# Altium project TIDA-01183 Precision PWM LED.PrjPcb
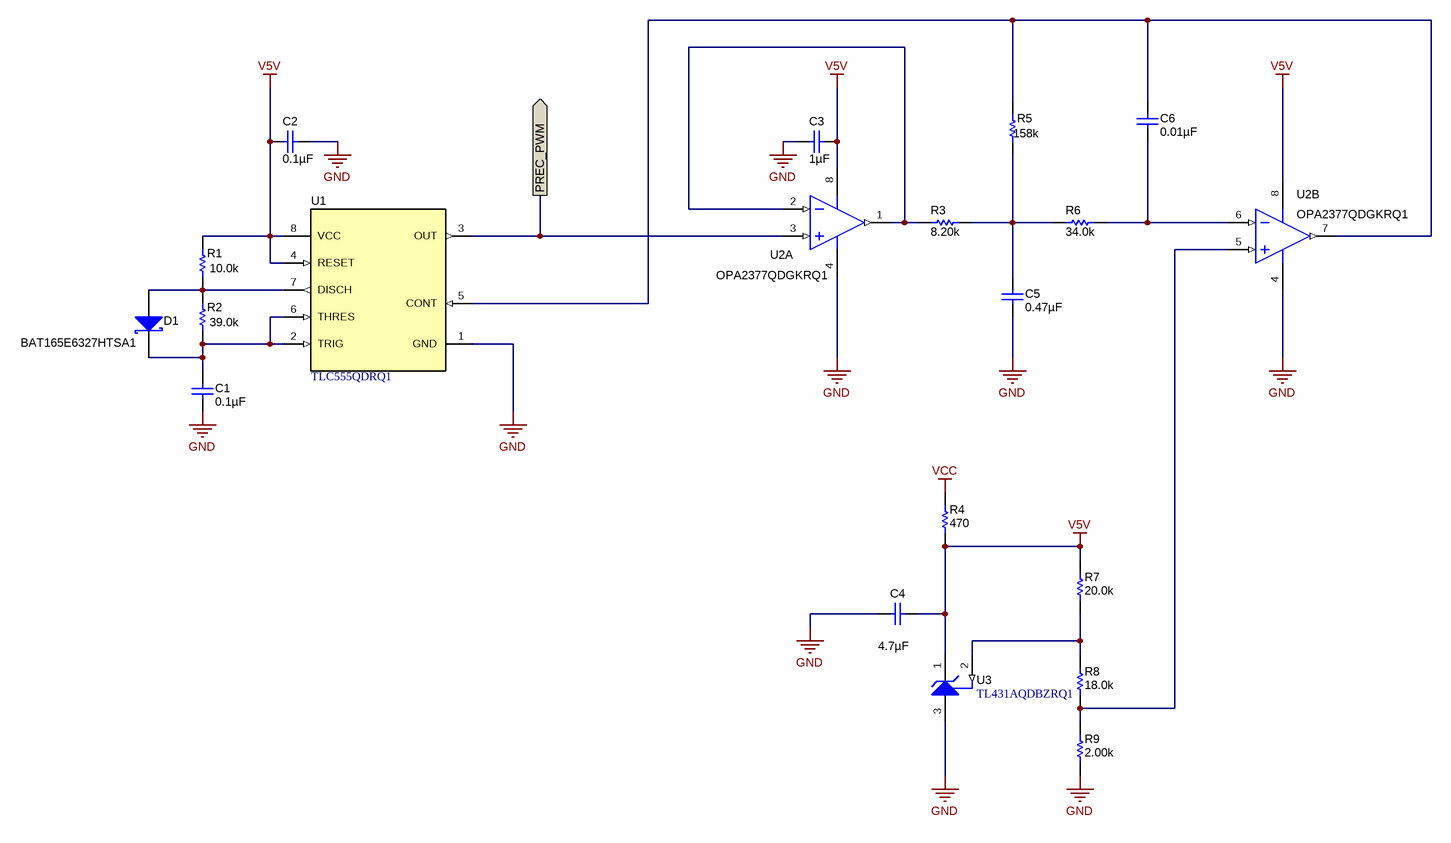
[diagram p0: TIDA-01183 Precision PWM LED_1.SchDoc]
CopyrightYear: 2016; EVM_Orderable: No; PCB_Layout: Robert Regensburger; PCB_Rev: B; PRJ_Customer: Public Release; PRJ_Engineer: Robert Regensburger; PRJ_Number: TIDA-01183; PRJ_Title: Precision PWM LED Dimming; SCH_Rev: B; TechSupport: http://www.ti.com/support; TID: N/A
3 sheets, 109 parts. Net scope: flat (ports and power ports of the same name join across sheets).
Board file: TIDA-01183 Precision PWM LED.PcbDoc
Sheets:
  TIDA-01183 Precision PWM LED_1.SchDoc
  TIDA-01183 Precision PWM LED_2.SchDoc
  TIDA-01183 Precision PWM LED_Hardware.SchDoc

## Sheet TIDA-01183 Precision PWM LED_1.SchDoc: Precision PWM Generator
size 431 x 279 mm; Date: Not shown in title block; ApprovedBy: Not shown in title block; CheckedBy: Not shown in title block; Author: Not shown in title block; CompanyName: Not shown in title block; DrawnBy: R. Regensburger; Engineer: Not shown in title block; Organization: Not shown in title block; Address1: Not shown in title block; Address2: Not shown in title block; Address3: Not shown in title block; Address4: Not shown in title block; DocumentNumber: 1; Revision: Use project parameter SCH_Rev; SheetNumber: 1; SheetTotal: 3; PageSetup: Record=PageOptions¦CenterHorizontal=True¦CenterVertical=True¦PrintScale=0.96¦XCorrection=1.00¦YCorrection=1.00¦PrintKind=0¦BorderSize=5000000¦LeftOffset=0¦BottomOffset=0¦Orientation=2¦PaperLength=1000¦PaperWidth=1000¦Scale=100¦PaperSource=15¦PrintQuality=-3¦MediaType=1¦DitherType=10¦PrintScaleMode=1¦PaperKind=11x17¦PaperIndex=3

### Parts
C1  ValueDisplayed: 0.1µF  [1206_190]  (hidden comment: C3216C0G2A104J160AC)
C2  ValueDisplayed: 0.1µF  [0603]  (hidden comment: 0603YC104JAT2A)
C3  ValueDisplayed: 1µF  [0603]  (hidden comment: GRM188R71C105KA12D)
C4  ValueDisplayed: 4.7µF  [0603]  (hidden comment: GRM188R61C475KAAJ)
C5  ValueDisplayed: 0.47µF  [0603]  (hidden comment: GRM188R71E474KA12D)
C6  ValueDisplayed: 0.01µF  [0603]  (hidden comment: GRM188R71C103KA01D)
D1  BAT165E6327HTSA1  [SOD-323]
R1  ValueDisplayed: 10.0k  [0603]  (hidden comment: CRCW060310K0FKEA)
R2  ValueDisplayed: 39.0k  [0603]  (hidden comment: RC0603FR-0739KL)
R3  ValueDisplayed: 8.20k  [0603]  (hidden comment: RC0603FR-078K2L)
R4  ValueDisplayed: 470  [0603]  (hidden comment: CRCW0603470RJNEA)
R5  ValueDisplayed: 158k  [0603]  (hidden comment: CRCW0603158KFKEA)
R6  ValueDisplayed: 34.0k  [0603]  (hidden comment: CRCW060334K0FKEA)
R7  ValueDisplayed: 20.0k  [0603]  (hidden comment: RG1608P-203-B-T5)
R8  ValueDisplayed: 18.0k  [0603]  (hidden comment: RG1608P-183-B-T5)
R9  ValueDisplayed: 2.00k  [0603]  (hidden comment: RG1608P-202-B-T5)
U1  TLC555QDRQ1  [D0008A_M]
U2  OPA2377QDGKRQ1  [DGK0008A_N]  (parts A,B of 2)
U3  TL431AQDBZRQ1  [DBZ0003A_N]

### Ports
PREC_PWM (out)

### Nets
GND: C1.2 C2.2 C3.1 C4.2 C5.2 R9.1 U1.1(GND) U2.4(V-) U3.3(ANODE)
V5V: C2.1 C3.2 C4.1 R1.2 R4.1 R7.2 U1.4(RESET) U1.8(VCC) U2.8(V+) U3.1(CATHODE)
VCC: R4.2
PREC_PWM: U1.3(OUT) U2.3(IN_A+) ; port PREC_PWM
NetC1_1: C1.1 D1.1(K) R2.1 U1.2(TRIG) U1.6(THRES)
NetC5_1: C5.1 R3.2 R5.1 R6.1
NetC6_1: C6.1 R5.2 U1.5(CONT) U2.7(OUT_B)
NetC6_2: C6.2 R6.2 U2.6(IN_B-)
NetD1_2: D1.2(A) R1.1 R2.2 U1.7(DISCH)
NetR3_1: R3.1 U2.1(OUT_A) U2.2(IN_A-)
NetR7_1: R7.1 R8.2 U3.2(REF)
NetR8_1: R8.1 R9.2 U2.5(IN_B+)

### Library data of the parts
C1 = C3216C0G2A104J160AC: CAP, CERM, 0.1 µF, 100 V, +/- 5%, C0G/NP0, 1206_190; Manufacturer: TDK; Polarized: N; CompType: Capacitor; Value: 0.1uF; U/M: EA; Cap_F: 0.0000001; Tolerance_%: 5; Value1: Unknown; VDC_V: 100; Value2: 100V; TaMin_C: -55; TaMax_C: 125; Cap_Case: 1206; SizeArea_mm2: 5.12; SizeAreaWB_mm2: 10.92; SizeX_mm: 3.2; SizeY_mm: 1.6; SizeZ_mm: 1.9; AEC Category: Q200
C2 = 0603YC104JAT2A: CAP, CERM, 0.1 µF, 16 V, +/- 5%, X7R, 0603; Manufacturer: AVX; Polarized: N; CompType: Capacitor; Value: 0.1uF; U/M: EA; Cap_F: 0.0000001; Tolerance_%: 5; ESR_ohm: 0.039; Value1: 0.039 ohm; VDC_V: 16; Value2: 16V; TaMin_C: -55; TaMax_C: 125; AEC Category: Q200
C3 = GRM188R71C105KA12D: CAP, CERM, 1 µF, 16 V, +/- 10%, X7R, 0603; Manufacturer: MuRata; Polarized: N; CompType: Capacitor; Value: 1uF; U/M: EA; Cap_F: 0.000001; Tolerance_%: 10; ESR_ohm: 0.011; Value1: 0.011 ohm; VDC_V: 16; Value2: 16V; TaMin_C: -55; TaMax_C: 125; AEC Category: Q200
C4 = GRM188R61C475KAAJ: CAP, CERM, 4.7 µF, 16 V, +/- 10%, X5R, 0603; Manufacturer: MuRata; Polarized: N; CompType: Capacitor; Value: 4.7uF; U/M: EA; Cap_F: 0.0000047; Tolerance_%: 10; Value1: Unknown; VDC_V: 16; Value2: 16V; TaMin_C: -55; TaMax_C: 85; AEC Category: Q200
C5 = GRM188R71E474KA12D: CAP, CERM, 0.47 µF, 25 V, +/- 10%, X7R, 0603; Manufacturer: MuRata; Polarized: N; CompType: Capacitor; Value: 0.47uF; U/M: EA; Cap_F: 0.00000047; Tolerance_%: 10; Value1: Unknown; VDC_V: 25; Value2: 25V; TaMin_C: -55; TaMax_C: 125; AEC Category: Q200
C6 = GRM188R71C103KA01D: CAP, CERM, 0.01 µF, 16 V, +/- 10%, X7R, 0603; Manufacturer: MuRata; Polarized: N; CompType: Capacitor; Value: 0.01uF; U/M: EA; Cap_F: 0.00000001; Tolerance_%: 10; Value1: Unknown; VDC_V: 16; Value2: 16V; TaMin_C: -55; TaMax_C: 125; AEC Category: Q200
D1 = BAT165E6327HTSA1: Diode, Schottky, 40 V, 0.75 A, AEC-Q101, SOD-323; Manufacturer: Infineon Technologies; U/M: EA; Vf_V: 0.74; Value: 40V; Value1: 0.75A; Value2: 0.74V; Io_A: 0.75; Vr_V: 40; TJmax_C: 150; SizeAreaWB_mm2: 8.695; SizeArea_mm2: 3.645; SizeX_mm: 2.7; SizeY_mm: 1.35; SizeZ_mm: 1; AEC Category: Q101; AEC Qualified: Y
R1 = CRCW060310K0FKEA: RES, 10.0 k, 1%, 0.1 W, 0603; Manufacturer: Vishay-Dale; CompType: Resistor; Value: 10.0k; Res_ohm: 10000; Value_Code: 10k0; Tolerance_%: 1; Power_W: 0.1; Value2: 0.1W; VDC_V: 75; TempCo: 100 ppm/C; SizeArea_mm2: 1.28; SizeX_mm: 1.6; SizeY_mm: 0.8; EIA_Code: E96; U/M: EA; AEC Category: Q200
R2 = RC0603FR-0739KL: RES, 39.0 k, 1%, 0.1 W, 0603; Manufacturer: Yageo America; CompType: Resistor; Value: 39.0k; Res_ohm: 39000; Value_Code: 39k0; Tolerance_%: 1; Power_W: 0.1; Value2: 0.1W; VDC_V: 150; TempCo: 200 ppm/C; SizeArea_mm2: 1.28; SizeX_mm: 1.6; SizeY_mm: 0.8; U/M: EA; AEC Category: Q200
R3 = RC0603FR-078K2L: RES, 8.20 k, 1%, 0.1 W, 0603; Manufacturer: Yageo America; CompType: Resistor; Value: 8.20k; Res_ohm: 8200; Value_Code: 8k20; Tolerance_%: 1; Power_W: 0.1; Value2: 0.1W; VDC_V: 150; TempCo: 200 ppm/C; U/M: EA; AEC Category: Q200
R4 = CRCW0603470RJNEA: RES, 470, 5%, 0.1 W, 0603; Manufacturer: Vishay-Dale; CompType: Resistor; Value: 470; Value_Code: 470R; Tolerance_%: 5; Power_W: 0.1; Value2: 0.1W; VDC_V: 75; TempCo: 200 ppm/C; EIA_Code: E24; U/M: EA; AEC Category: Q200
R5 = CRCW0603158KFKEA: RES, 158 k, 1%, 0.1 W, 0603; Manufacturer: Vishay-Dale; CompType: Resistor; Value: 158k; Res_ohm: 158000; Tolerance_%: 1; Power_W: 0.1; Value2: 0.1W; VDC_V: 75; TempCo: 100 ppm/C; EIA_Code: E96; U/M: EA; AEC Category: Q200
R6 = CRCW060334K0FKEA: RES, 34.0 k, 1%, 0.1 W, 0603; Manufacturer: Vishay-Dale; CompType: Resistor; Value: 34.0k; Res_ohm: 34000; Value_Code: 34k0; Tolerance_%: 1; Power_W: 0.1; Value2: 0.1W; VDC_V: 75; TempCo: 100 ppm/C; EIA_Code: E96; U/M: EA; AEC Category: Q200
R7 = RG1608P-203-B-T5: RES, 20.0 k, 0.1%, 0.1 W, 0603; Manufacturer: Susumu Co Ltd; CompType: Resistor; Value: 20.0k; Res_ohm: 20000; Value_Code: 20k0; Tolerance_%: 0.1; Value2: 0.1W; VDC_V: 75; TempCo: 25 ppm/C; EIA_Code: E192; U/M: EA; AEC Category: Q200
R8 = RG1608P-183-B-T5: RES, 18.0 k, 0.1%, 0.1 W, 0603; Manufacturer: Susumu Co Ltd; CompType: Resistor; Value: 18.0k; Res_ohm: 18000; Value_Code: 18k0; Tolerance_%: 0.1; Value2: 0.1W; VDC_V: 75; TempCo: 25 ppm/C; EIA_Code: E192; U/M: EA; AEC Category: Q200
R9 = RG1608P-202-B-T5: RES, 2.00 k, 0.1%, 0.1 W, 0603; Manufacturer: Susumu Co Ltd; CompType: Resistor; Value: 2.00k; Res_ohm: 2000; Value_Code: 2k00; Tolerance_%: 0.1; Value2: 0.1W; VDC_V: 75; TempCo: 25 ppm/C; EIA_Code: E192; U/M: EA; AEC Category: Q200
U1 = TLC555QDRQ1: LinCMOS Timer, D0008A; Manufacturer: Texas Instruments; SymbolCreator: a0799628; CompType: IC; U/M: EA
U2 = OPA2377AIDGKR: Low-Cost, Low Noise, 5 MHz CMOS Operational Amplifier, 2.2 to 5.5 V, -40 to 125 degC, 8-pin SOP (DGK0008A), Green (RoHS & no Sb/Br); Manufacturer: Texas Instruments; Alternate PartNumber: Equivalent; CMRR(Min)(dB): 70; IIB(Max)(pA): 10; Iq per channel(Max)(mA): 1.05; Number of Channels: 2; Offset Drift(Typ)(uV/C): 0.32; Sub Family: Low Input Bias Current Amp (<=10pA), Low Noise Amp (<=10nV/rtHz), Low Supply Voltage Amplifier (<=2.7V), Precision Amplifier; Total Supply Voltage(Max)(+5V is 5, +/-5V is 10): 5.5; Total Supply Voltage(Min)(+5V is 5, +/-5V is 10): 2.2; Vio (25C)(Max)(mV): 1; Vn at 1kHz(Typ)(nV/rtHz): 7.5
U3 = TL431AQDBZRQ1: Automotive Catalog Adjustable Precision Shunt Regulator, 34 ppm / degC, 100 mA, -40 to 125 degC, 3-pin SOT-23 (DBZ), Green (RoHS & no Sb/Br); Manufacturer: Texas Instruments; Alternate PartNumber: Equivalent; Iout/Iz(Max)(mA): 100; Min Iz for Regulation(uA): 600; SubFamily: Shunt Voltage Reference; Temp Coeff(Typ)(ppm/ degree C): 34; VO Adj(Max)(V): 36; VO Adj(Min)(V): 2.495; Initial Accuracy @ 25/deg C(%): 1

## Sheet TIDA-01183 Precision PWM LED_2.SchDoc: Buck-Boost LED Driver
size 431 x 279 mm; Date: Not shown in title block; ApprovedBy: Not shown in title block; CheckedBy: Not shown in title block; Author: Not shown in title block; CompanyName: Not shown in title block; DrawnBy: R. Regensburger; Engineer: Not shown in title block; Organization: Not shown in title block; Address1: Not shown in title block; Address2: Not shown in title block; Address3: Not shown in title block; Address4: Not shown in title block; DocumentNumber: 2; Revision: Use project parameter SCH_Rev; SheetNumber: 2; SheetTotal: 3; PageSetup: Record=PageOptions¦CenterHorizontal=True¦CenterVertical=True¦PrintScale=0.61¦XCorrection=1.00¦YCorrection=1.00¦PrintKind=0¦BorderSize=5000000¦LeftOffset=0¦BottomOffset=0¦Orientation=2¦PaperLength=1000¦PaperWidth=1000¦Scale=100¦PaperSource=15¦PrintQuality=600¦MediaType=1¦DitherType=10¦PrintScaleMode=1¦PaperKind=Letter
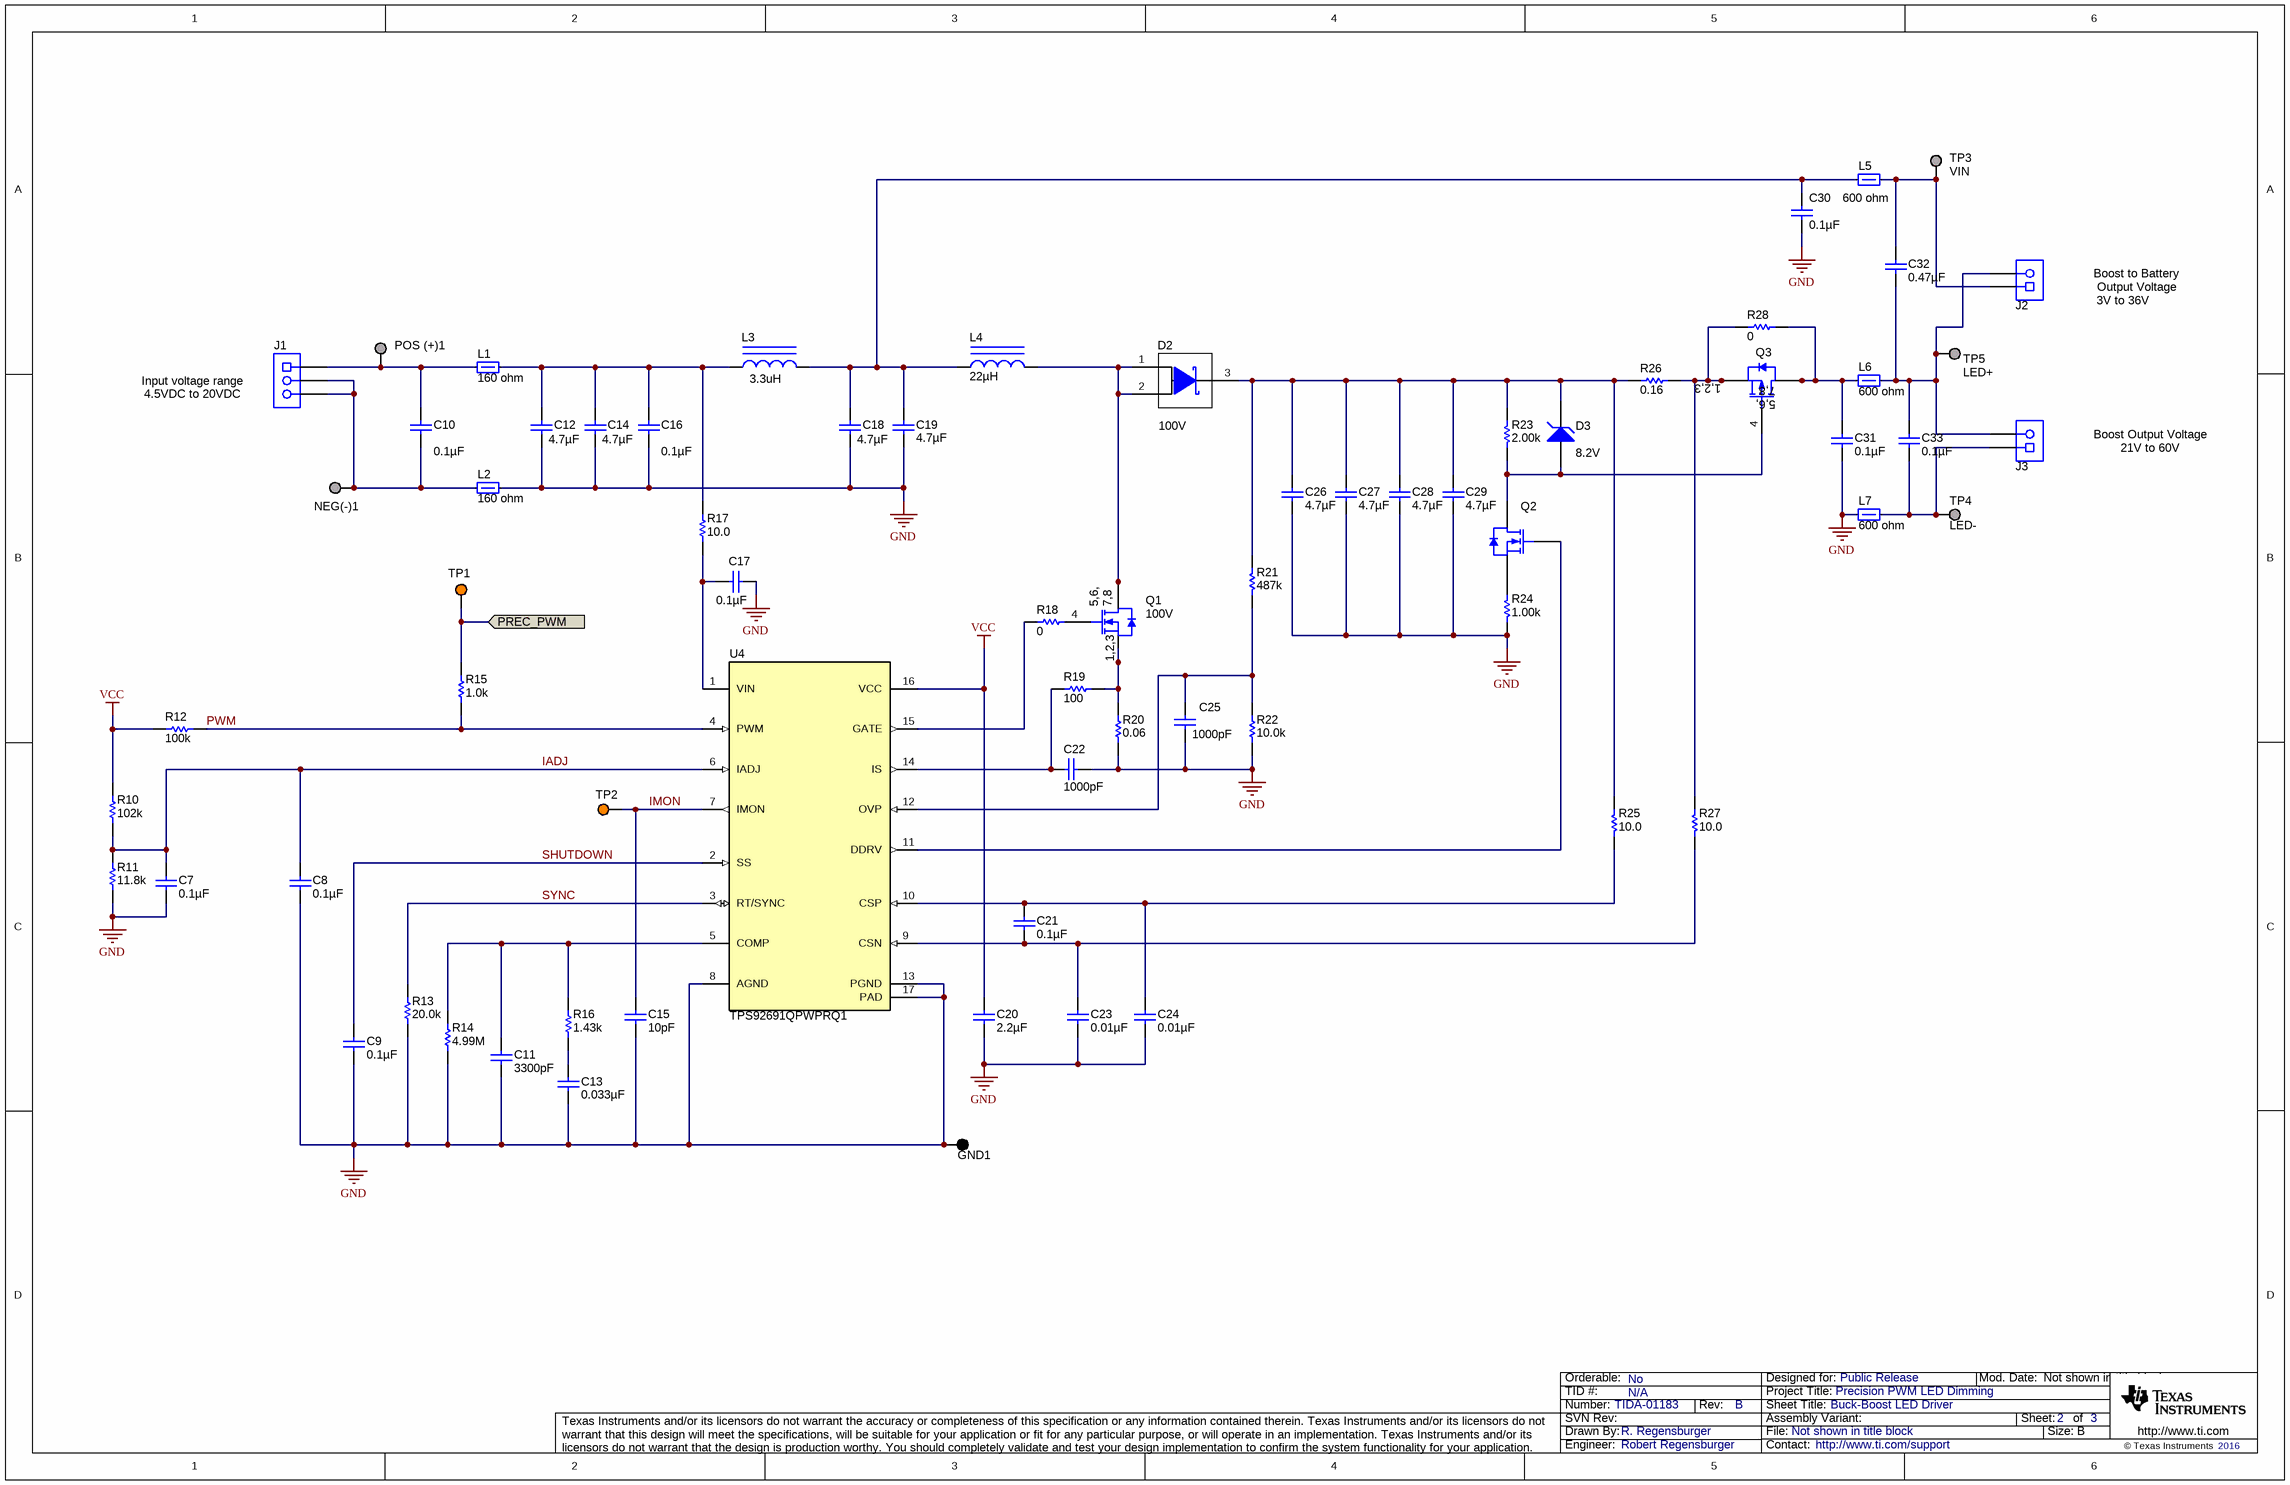
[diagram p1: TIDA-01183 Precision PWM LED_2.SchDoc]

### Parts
C7  ValueDisplayed: 0.1µF  [0603]  (hidden comment: 06033C104JAT2A)
C8  ValueDisplayed: 0.1µF  [0603]  (hidden comment: 06033C104JAT2A)
C9  ValueDisplayed: 0.1µF  [0603]  (hidden comment: 06033C104JAT2A)
C10  ValueDisplayed: 0.1µF  [0805_HV]  (hidden comment: C2012X7R2A104K125AA)
C11  ValueDisplayed: 3300pF  [0603]  (hidden comment: GRM188R71E332KA01D)
C12  ValueDisplayed: 4.7µF  [1210]  (hidden comment: C3225X7S2A475K200AE)
C13  ValueDisplayed: 0.033µF  [0805_HV]  (hidden comment: GRM216R71E333KA01D)
C14  ValueDisplayed: 4.7µF  [1210]  (hidden comment: C3225X7S2A475K200AE)
C15  ValueDisplayed: 10pF  [0603]  (hidden comment: 06035A100JAT2A)
C16  ValueDisplayed: 0.1µF  [0805_HV]  (hidden comment: C2012X7R2A104K125AA)
C17  ValueDisplayed: 0.1µF  [0805_HV]  (hidden comment: C2012X7R2A104K125AA)
C18  ValueDisplayed: 4.7µF  [1210]  (hidden comment: C3225X7S2A475K200AE)
C19  ValueDisplayed: 4.7µF  [1210]  (hidden comment: C3225X7S2A475K200AE)
C20  ValueDisplayed: 2.2µF  [0805_HV]  (hidden comment: C0805C225K4RACTU)
C21  ValueDisplayed: 0.1µF  [0603]  (hidden comment: GRM188R71H104KA93D)
C22  ValueDisplayed: 1000pF  [0603]  (hidden comment: GRM1885C2A102JA01D)
C23  ValueDisplayed: 0.01µF  [0603]  (hidden comment: CGA3E2X7R2A103K080AA)
C24  ValueDisplayed: 0.01µF  [0603]  (hidden comment: CGA3E2X7R2A103K080AA)
C25  ValueDisplayed: 1000pF  [0603_HV]  (hidden comment: C1608C0G2A102J080AA)
C26  ValueDisplayed: 4.7µF  [1210]  (hidden comment: C3225X7S2A475K200AE)
C27  ValueDisplayed: 4.7µF  [1210]  (hidden comment: C3225X7S2A475K200AE)
C28  ValueDisplayed: 4.7µF  [1210]  (hidden comment: C3225X7S2A475K200AE)
C29  ValueDisplayed: 4.7µF  [1210]  (hidden comment: C3225X7S2A475K200AE)
C30  ValueDisplayed: 0.1µF  [1206_180]  (hidden comment: C3216X7R2A104K160AA)
C31  ValueDisplayed: 0.1µF  [1206_180]  (hidden comment: C3216X7R2A104K160AA)
C32  ValueDisplayed: 0.47µF  [1206_180]  (hidden comment: C3216X7R2A474K160AA)
C33  ValueDisplayed: 0.1µF  [1206_180]  (hidden comment: C3216X7R2A104K160AA)
D2  value 100V  [PowerDI5]  (hidden comment: PDS3100Q-13)
D3  value 8.2V  [sod-323]  (hidden comment: MMSZ5237BS-7-F)
GND1  5001  [Keystone5001]  (value not drawn)
J1  1727023  [Phoenix_1727023]  (value not drawn)
J2  1727010  [PhoenixConact_1727010]  (value not drawn)
J3  1727010  [PhoenixConact_1727010]  (value not drawn)
L1  value 160 ohm  [1206]  (hidden comment: HI1206T161R-10)
L2  value 160 ohm  [1206]  (hidden comment: HI1206T161R-10)
L3  value 3.3uH  [CLF7045]  (hidden comment: CLF7045T-3R3N)
L4  ValueDisplayed: 22µH  [IHLP-4040DZ]  (hidden comment: IHLP4040DZER220M8A)
L5  value 600 ohm  [1206]  (hidden comment: MI1206K601R-10)
L6  value 600 ohm  [1206]  (hidden comment: MI1206K601R-10)
L7  value 600 ohm  [1206]  (hidden comment: MI1206K601R-10)
NEG(-)1  GND  [Keystone1502-2]  (value not drawn)
POS_(+)1  Suggest using a net name here  [Keystone1502-2]  (value not drawn)
Q1  value 100V  [PowerFLAT5x6_R]  (hidden comment: STL8N10LF3)
Q2  DMN10H220L-7  [SOT-23]  (value not drawn)
Q3  SI7415DN-T1-GE3  [PowerPAK_1212-8]  (value not drawn)
R10  ValueDisplayed: 102k  [0603]  (hidden comment: CRCW0603102KFKEA)
R11  ValueDisplayed: 11.8k  [0603]  (hidden comment: CRCW060311K8FKEA)
R12  ValueDisplayed: 100k  [0603]  (hidden comment: CRCW0603100KFKEA)
R13  ValueDisplayed: 20.0k  [0603]  (hidden comment: CRCW060320K0FKEA)
R14  ValueDisplayed: 4.99M  [0603]  (hidden comment: CRCW06034M99FKEA)
R15  ValueDisplayed: 1.0k  [0603]  (hidden comment: CRCW06031K00JNEA)
R16  ValueDisplayed: 1.43k  [0603]  (hidden comment: CRCW06031K43FKEA)
R17  ValueDisplayed: 10.0  [1206]  (hidden comment: CRCW120610R0FKEA)
R18  ValueDisplayed: 0  [0603_HV]  (hidden comment: CRCW06030000Z0EA)
R19  ValueDisplayed: 100  [0603_HV]  (hidden comment: CRCW0603100RFKEA)
R20  ValueDisplayed: 0.06  [2010]  (hidden comment: CSRN2010FK60L0)
R21  ValueDisplayed: 487k  [0603_HV]  (hidden comment: CRCW0603487KFKEA)
R22  ValueDisplayed: 10.0k  [0603_HV]  (hidden comment: CRCW060310K0FKEA)
R23  ValueDisplayed: 2.00k  [0603_HV]  (hidden comment: CRCW06032K00FKEA)
R24  ValueDisplayed: 1.00k  [1206]  (hidden comment: CRCW12061K00FKEA)
R25  ValueDisplayed: 10.0  [0603_HV]  (hidden comment: CRCW060310R0FKEA)
R26  ValueDisplayed: 0.16  [1210]  (hidden comment: MCR25JZHFLR160)
R27  ValueDisplayed: 10.0  [0603_HV]  (hidden comment: CRCW060310R0FKEA)
R28  ValueDisplayed: 0  [1206]  (hidden comment: CRCW12060000Z0EA)
TP1  5003  [Keystone5003]  (value not drawn)
TP2  5003  [Keystone5003]  (value not drawn)
TP3  VIN  [Keystone1502-2]
TP4  LED-  [Keystone1502-2]
TP5  LED+  [Keystone1502-2]
U4  TPS92691QPWPRQ1  [PWP0016J_N]

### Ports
PREC_PWM (in)

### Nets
GND: C7.2 C8.2 C9.2 C11.2 C12.2 C13.1 C14.2 C15.2 C16.2 C17.1 C18.2 C19.2 C20.2 C22.2 C23.2 C24.2 C25.2 C26.1 C27.1 C28.1 C29.1 C30.2 C31.2 GND1.1 L2.2 L7.1 R11.1 R13.1 R14.1 R20.1 R22.1 R24.1 U4.8(AGND) U4.13(PGND) U4.17(PAD)
VCC: C20.1 R10.2 R12.1 U4.16(VCC)
IADJ: C7.1 C8.1 R10.1 R11.2 U4.6(IADJ)
IMON: C15.1 TP2.1 U4.7(IMON)
PREC_PWM: R15.1 TP1.1 ; port PREC_PWM
PWM: R12.2 R15.2 U4.4(PWM)
SHUTDOWN: C9.1 U4.2(SS)
SYNC: R13.2 U4.3(RT/SYNC)
NetC10_1: C10.1 J1.1 L1.1 POS_(+)1.1
NetC10_2: C10.2 J1.2 J1.3 L2.1 NEG(-)1.1
NetC11_1: C11.1 R14.2 R16.2 U4.5(COMP)
NetC12_1: C12.1 C14.1 C16.1 L1.2 L3.1 R17.2
NetC13_2: C13.2 R16.1
NetC17_2: C17.2 R17.1 U4.1(VIN)
NetC18_1: C18.1 C19.1 C30.1 L3.2 L4.1 L5.1
NetC21_1: C21.1 C24.1 R25.1 U4.10(CSP)
NetC21_2: C21.2 C23.1 R27.1 U4.9(CSN)
NetC22_1: C22.1 R19.1 U4.14(IS)
NetC25_1: C25.1 R21.1 R22.2 U4.12(OVP)
NetC26_2: C26.2 C27.2 C28.2 C29.2 D2.3(K) D3.1(K) R21.2 R23.2 R25.2 R26.1
NetC31_1: C31.1 L6.1 Q3.5(D) Q3.6(D) Q3.7(D) Q3.8(D) Q3.9(D) R28.1
NetC32_1: C32.1 J2.1 L5.2 TP3.1
NetC32_2: C32.2 C33.1 J2.2 J3.2 L6.2 TP5.1
NetC33_2: C33.2 J3.1 L7.2 TP4.1
NetD2_1: D2.1(A) D2.2(A) L4.2 Q1.5(D) Q1.6(D) Q1.7(D) Q1.8(D) Q1.9(D)
NetD3_2: D3.2(A) Q2.3(D) Q3.4(G) R23.1
NetQ1_1: Q1.1(S) Q1.2(S) Q1.3(S) R19.2 R20.2
NetQ1_4: Q1.4(G) R18.2
NetQ2_1: Q2.1(G) U4.11(DDRV)
NetQ2_2: Q2.2(S) R24.2
NetQ3_1: Q3.1(S) Q3.2(S) Q3.3(S) R26.2 R27.2 R28.2
NetR18_1: R18.1 U4.15(GATE)

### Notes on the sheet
- 3V to 36V
- Boost to Battery
- Output Voltage
- 4.5VDC to 20VDC
- (near J1) Input voltage range
- Boost Output Voltage
- 21V to 60V

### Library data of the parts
C7-C9 = 06033C104JAT2A: CAP, CERM, 0.1 µF, 25 V, +/- 5%, X7R, 0603; Manufacturer: AVX; Polarized: N; CompType: Capacitor; Value: 0.1uF; U/M: EA; Cap_F: 0.0000001; Tolerance_%: 5; ESR_ohm: 0.05; Value1: 0.05 ohm; VDC_V: 25; Value2: 25V; TaMin_C: -55; TaMax_C: 125; SizeArea_mm2: 1.28; SizeAreaWB_mm2: 4.68; SizeX_mm: 1.6; SizeY_mm: 0.8; SizeZ_mm: 1; AEC Category: Q200
C10 C16 C17 = C2012X7R2A104K125AA: CAP, CERM, 0.1 µF, 100 V, +/- 10%, X7R, 0805; Manufacturer: TDK; Polarized: N; CompType: Capacitor; Value: 0.1uF; U/M: EA; Cap_F: 0.0000001; Tolerance_%: 10; ESR_ohm: 0.0158; Value1: 0.0158 ohm; VDC_V: 100; Value2: 100V; TaMin_C: -55; TaMax_C: 125; Cap_Case: 0805; AEC Category: Q200
C11 = GRM188R71E332KA01D: CAP, CERM, 3300 pF, 25 V, +/- 10%, X7R, 0603; Manufacturer: MuRata; Polarized: N; CompType: Capacitor; Value: 3300pF; U/M: EA; Cap_F: 0.0000000033; Tolerance_%: 10; Value1: Unknown; VDC_V: 25; Value2: 25V; TaMin_C: -55; TaMax_C: 125; AEC Category: Q200
C12 C14 C18 C19 C26-C29 = C3225X7S2A475K200AE: CAP, CERM, 4.7 µF, 100 V, +/- 10%, X7S, 1210; Manufacturer: TDK; Polarized: N; CompType: Capacitor; Value: 4.7uF; U/M: EA; Cap_F: 0.0000047; Tolerance_%: 10; Value1: Unknown; VDC_V: 100; Value2: 100V; TaMin_C: -55; TaMax_C: 125
C13 = GRM216R71E333KA01D: CAP, CERM, 0.033 µF, 25 V, +/- 10%, X7R, 0805; Manufacturer: MuRata; Polarized: N; CompType: Capacitor; Value: 0.033uF; U/M: EA; Cap_F: 0.000000033; Tolerance_%: 10; Value1: Unknown; VDC_V: 25; Value2: 25V; TaMin_C: -55; TaMax_C: 125; Cap_Case: 0805
C15 = 06035A100JAT2A: CAP, CERM, 10 pF, 50 V, +/- 5%, C0G/NP0, 0603; Manufacturer: AVX; Polarized: N; CompType: Capacitor; Value: 10pF; U/M: EA; Cap_F: 0.00000000001; Tolerance_%: 5; ESR_ohm: 0.403; Value1: 0.403 ohm; VDC_V: 50; Value2: 50V; TaMin_C: -55; TaMax_C: 125; SizeArea_mm2: 1.28; SizeAreaWB_mm2: 4.68; SizeX_mm: 1.6; SizeY_mm: 0.8; SizeZ_mm: 1; AEC Category: Q200
C20 = C0805C225K4RACTU: CAP, CERM, 2.2 µF, 16 V, +/- 10%, X7R, 0805; Manufacturer: Kemet; Polarized: N; CompType: Capacitor; Value: 2.2uF; U/M: EA; Cap_F: 0.0000022; Tolerance_%: 10; ESR_ohm: 0.008; Value1: 0.008 ohm; VDC_V: 16; Value2: 16V; IRMS_A: 15.55; TaMin_C: -55; TaMax_C: 125; Cap_Case: 0805; SizeArea_mm2: 2.5; SizeAreaWB_mm2: 6.75; SizeX_mm: 2; SizeY_mm: 1.25; SizeZ_mm: 1.45; AEC Category: Q200
C21 = GRM188R71H104KA93D: CAP, CERM, 0.1 µF, 50 V, +/- 10%, X7R, 0603; Manufacturer: MuRata; Polarized: N; CompType: Capacitor; Value: 0.1uF; U/M: EA; Cap_F: 0.0000001; Tolerance_%: 10; Value1: Unknown; VDC_V: 50; Value2: 50V; TaMin_C: -55; TaMax_C: 125; SizeArea_mm2: 1.28; SizeAreaWB_mm2: 4.68; SizeX_mm: 1.6; SizeY_mm: 0.8; SizeZ_mm: 1; AEC Category: Q200
C22 = GRM1885C2A102JA01D: CAP, CERM, 1000 pF, 100 V, +/- 5%, C0G/NP0, 0603; Manufacturer: MuRata; Polarized: N; CompType: Capacitor; Value: 1000pF; U/M: EA; Cap_F: 0.000000001; Tolerance_%: 5; Value1: Unknown; VDC_V: 100; Value2: 100V; TaMin_C: -55; TaMax_C: 125; SizeArea_mm2: 1.28; SizeAreaWB_mm2: 4.68; SizeX_mm: 1.6; SizeY_mm: 0.8; SizeZ_mm: 1; AEC Category: Q200
C23 C24 = CGA3E2X7R2A103K080AA: CAP, CERM, 0.01 µF, 100 V, +/- 10%, X7R, AEC-Q200 Grade 1, 0603; Manufacturer: TDK; Polarized: N; CompType: Capacitor; Value: 0.01uF; U/M: EA; Cap_F: 0.00000001; Tolerance_%: 10; ESR_ohm: 0.235428; Value1: 0.235428 ohm; VDC_V: 100; Value2: 100V; IRMS_A: 0.396995; TaMin_C: -55; TaMax_C: 125; SizeArea_mm2: 1.28; SizeAreaWB_mm2: 4.68; SizeX_mm: 1.6; SizeY_mm: 0.8; SizeZ_mm: 1; AEC Category: Q200; AEC Qualified: Y
C25 = C1608C0G2A102J080AA: CAP, CERM, 1000 pF, 100 V, +/- 5%, C0G/NP0, 0603; Manufacturer: TDK; Polarized: N; CompType: Capacitor; Value: 1000pF; U/M: EA; Cap_F: 0.000000001; Tolerance_%: 5; ESR_ohm: 0.0589; Value1: 0.0589 ohm; VDC_V: 100; Value2: 100V; TaMin_C: -55; TaMax_C: 125; Cap_Case: 0603; SizeArea_mm2: 1.28; SizeAreaWB_mm2: 4.68; SizeX_mm: 1.6; SizeY_mm: 0.8; SizeZ_mm: 1; AEC Category: Q200
C30 C31 C33 = C3216X7R2A104K160AA: CAP, CERM, 0.1 µF, 100 V, +/- 10%, X7R, 1206; Manufacturer: TDK; Polarized: N; CompType: Capacitor; Value: 0.1uF; U/M: EA; Cap_F: 0.0000001; Tolerance_%: 10; ESR_ohm: 0.030343; Value1: 0.030343 ohm; VDC_V: 100; Value2: 100V; IRMS_A: 1.33802; TaMin_C: -55; TaMax_C: 125; SizeArea_mm2: 5.12; SizeAreaWB_mm2: 10.92; SizeX_mm: 3.2; SizeY_mm: 1.6; SizeZ_mm: 1.8; AEC Category: Q200
C32 = C3216X7R2A474K160AA: CAP, CERM, 0.47 µF, 100 V, +/- 10%, X7R, 1206; Manufacturer: TDK; Polarized: N; CompType: Capacitor; Value: 0.47uF; U/M: EA; Cap_F: 0.00000047; Tolerance_%: 10; ESR_ohm: 0.007558; Value1: 0.007558 ohm; VDC_V: 100; Value2: 100V; IRMS_A: 2.64716; TaMin_C: -55; TaMax_C: 125; SizeArea_mm2: 5.12; SizeAreaWB_mm2: 10.92; SizeX_mm: 3.2; SizeY_mm: 1.6; SizeZ_mm: 1.8; AEC Category: Q200
D2 = PDS3100Q-13: Diode, Schottky, 100 V, 3 A, AEC-Q101, PowerDI5; Manufacturer: Diodes Inc.; U/M: EA; Vf_V: 0.76; Value1: 3A; Value2: 0.76V; Io_A: 3; Vr_V: 100; TJmax_C: 150; AEC Category: Q101; AEC Qualified: Y
D3 = MMSZ5237BS-7-F: Diode, Zener, 8.2 V, 200 mW, SOD-323; Manufacturer: Diodes Inc.; SymbolCreator: a0412235; U/M: EA; Power_W: 0.2; Vz_V: 8.2; Value1: 0.2W; RJA_CperW: 350
GND1 = 5001: Test Point, Miniature, Black, TH; Manufacturer: Keystone; CompType: Test Point Loop; U/M: EA
J1 = 1727023: Terminal Block Receptacle, 3x1, 3.81mm, R/A, TH; Manufacturer: Phoenix Contact; SymbolCreator: a0412235
J2 J3 = 1727010: Conn Term Block, 2POS, 3.81mm, TH; Manufacturer: Phoenix Contact; SymbolCreator: a0412235; CompType: Terminal Block
L1 L2 = HI1206T161R-10: Ferrite Bead, 160 ohm @ 100 MHz, 6 A, 1206; Manufacturer: Laird-Signal Integrity Products; Imax_A: 6; DCR_ohm: 0.018; Value1: 0.018 ohm; Value2: 6A; ZTyp@100MHz_Ohm: 160; Ztyp@1GHz_Ohm: 127
L3 = CLF7045T-3R3N: Inductor, Shielded, Ferrite, 3.3 µH, 5 A, 0.0213 ohm, SMD; Manufacturer: TDK; Ind_H: 3.3E-6; ValueDisplayed: 3.3µH; Imax_A: 5; Irms: 4.1A @ 30C rise; Isat: 5A @ 10% inductance drop; DCR_ohm: 0.0213; Value2: 5A
L4 = IHLP4040DZER220M8A: Inductor, Shielded Drum Core, Powdered Iron, 22 µH, 4.1 A, 0.0705 ohm, AEC-Q200 Grade 0, SMD; Manufacturer: Vishay-Dale; Value: 22uH; Ind_H: 22.0E-6; Imax_A: 4.1; Irms: 4.1A @ 40C rise; Isat: 6.4A @ 20% inductance drop; DCR_ohm: 0.0705; Value2: 4.1A; AEC Category: Q200; AEC Qualified: Y; AEC Grade: 0
L5-L7 = MI1206K601R-10: Ferrite Bead, 600 ohm @ 100 MHz, 1.5 A, 1206; Manufacturer: Laird-Signal Integrity Products; Imax_A: 1.5; DCR_ohm: 0.08; Value1: 0.08 ohm; Value2: 1.5A; ZTyp@100MHz_Ohm: 600; Ztyp@1GHz_Ohm: 130
NEG(-)1 POS_(+)1 TP3-TP5 = 1502-2: Terminal, Turret, TH, Double; Manufacturer: Keystone; CompType: Turret Terminal; U/M: EA
Q1 = STL8N10LF3: MOSFET, N-CH, 100 V, 20 A, AEC-Q101, 8-PowerVDFN; Manufacturer: STMicroelectronics; Alternate Manufacturer: None; U/M: EA; ChType: N; VdsMax_V: 100; Value1: ? ohm; Value2: 20.5 nC; QgTyp_nC: 20.5; Vgs_V: 20; AEC Category: Q101; AEC Qualified: Y
Q2 = DMN10H220L-7: MOSFET, N-CH, 100 V, 1.4 A, SOT-23; Manufacturer: Diodes Inc.; Alternate Manufacturer: None; U/M: EA; ChType: N; Value: 100V; VdsMax_V: 100; Value1: 0.25 ohm; Rdson45_ohm: 0.25; Value2: 4.1 nC; QgTyp_nC: 4.1; Vgs_V: 16; IdsMax_A: 1.4
Q3 = SI7415DN-T1-GE3: MOSFET, P-CH, -60 V, -3.6 A, PowerPAK 1212; Manufacturer: Vishay-Siliconix; Alternate Manufacturer: None; U/M: EA; ChType: P; Value: -60V; Value1: 0.11 ohm; Rdson45_ohm: 0.11; Value2: 15 nC; QgTyp_nC: 15; Vgs_V: 20
R10 = CRCW0603102KFKEA: RES, 102 k, 1%, 0.1 W, 0603; Manufacturer: Vishay-Dale; CompType: Resistor; Value: 102k; Res_ohm: 102000; Tolerance_%: 1; Power_W: 0.1; Value2: 0.1W; VDC_V: 75; TempCo: 100 ppm/C; EIA_Code: E96; U/M: EA; AEC Category: Q200
R11 = CRCW060311K8FKEA: RES, 11.8 k, 1%, 0.1 W, 0603; Manufacturer: Vishay-Dale; CompType: Resistor; Value: 11.8k; Res_ohm: 11800; Value_Code: 11k8; Tolerance_%: 1; Power_W: 0.1; Value2: 0.1W; VDC_V: 75; TempCo: 100 ppm/C; EIA_Code: E96; U/M: EA; AEC Category: Q200
R12 = CRCW0603100KFKEA: RES, 100 k, 1%, 0.1 W, 0603; Manufacturer: Vishay-Dale; CompType: Resistor; Value: 100k; Res_ohm: 100000; Tolerance_%: 1; Power_W: 0.1; Value2: 0.1W; VDC_V: 75; TempCo: 100 ppm/C; EIA_Code: E96; U/M: EA
R13 = CRCW060320K0FKEA: RES, 20.0 k, 1%, 0.1 W, 0603; Manufacturer: Vishay-Dale; CompType: Resistor; Value: 20.0k; Res_ohm: 20000; Value_Code: 20k0; Tolerance_%: 1; Power_W: 0.1; Value2: 0.1W; VDC_V: 75; TempCo: 100 ppm/C; EIA_Code: E96; U/M: EA
R14 = CRCW06034M99FKEA: RES, 4.99 M, 1%, 0.1 W, 0603; Manufacturer: Vishay-Dale; CompType: Resistor; Value: 4.99Meg; Res_ohm: 4990000; Value_Code: 4M99; Tolerance_%: 1; Power_W: 0.1; Value2: 0.1W; VDC_V: 75; TempCo: 100 ppm/C; EIA_Code: E96; U/M: EA
R15 = CRCW06031K00JNEA: RES, 1.0 k, 5%, 0.1 W, 0603; Manufacturer: Vishay-Dale; CompType: Resistor; Value: 1.0k; Res_ohm: 1000; Value_Code: 1k00; Tolerance_%: 5; Power_W: 0.1; Value2: 0.1W; VDC_V: 75; TempCo: 200 ppm/C; EIA_Code: E24; U/M: EA
R16 = CRCW06031K43FKEA: RES, 1.43 k, 1%, 0.1 W, 0603; Manufacturer: Vishay-Dale; CompType: Resistor; Value: 1.43k; Res_ohm: 1430; Value_Code: 1k43; Tolerance_%: 1; Power_W: 0.1; Value2: 0.1W; VDC_V: 75; TempCo: 100 ppm/C; EIA_Code: E96; U/M: EA; AEC Category: Q200
R17 = CRCW120610R0FKEA: RES, 10.0, 1%, 0.25 W, 1206; Manufacturer: Vishay-Dale; CompType: Resistor; Value: 10.0; Res_ohm: 10; Value_Code: 10R0; Tolerance_%: 1; Power_W: 0.25; Value2: 0.25W; VDC_V: 200; TempCo: 100 ppm/C; EIA_Code: E96; U/M: EA
R18 = CRCW06030000Z0EA: RES, 0, 5%, 0.1 W, 0603; Manufacturer: Vishay-Dale; CompType: Resistor; Value: 0; Value_Code: 0000; Tolerance_%: 5; Power_W: 0.1; Value2: 0.1W; VDC_V: 75; TempCo: 200 ppm/C; EIA_Code: E24; U/M: EA; AEC Category: Q200
R19 = CRCW0603100RFKEA: RES, 100, 1%, 0.1 W, 0603; Manufacturer: Vishay-Dale; CompType: Resistor; Value: 100; Value_Code: 100R; Tolerance_%: 1; Power_W: 0.1; Value2: 0.1W; VDC_V: 75; TempCo: 100 ppm/C; EIA_Code: E96; U/M: EA; AEC Category: Q200
R20 = CSRN2010FK60L0: RES, 0.06, 1%, 1 W, 2010; Manufacturer: Stackpole Electronics Inc; CompType: Resistor; Value: 0.06; Value_Code: R060; Tolerance_%: 1; Value2: 1W; TempCo: 250 ppm/C; U/M: EA
R21 = CRCW0603487KFKEA: RES, 487 k, 1%, 0.1 W, 0603; Manufacturer: Vishay-Dale; CompType: Resistor; Value: 487k; Res_ohm: 487000; Tolerance_%: 1; Power_W: 0.1; Value2: 0.1W; VDC_V: 75; TempCo: 100 ppm/C; EIA_Code: E96; U/M: EA
R22 = CRCW060310K0FKEA: RES, 10.0 k, 1%, 0.1 W, 0603; Manufacturer: Vishay-Dale; CompType: Resistor; Value: 10.0k; Res_ohm: 10000; Value_Code: 10k0; Tolerance_%: 1; Power_W: 0.1; Value2: 0.1W; VDC_V: 75; TempCo: 100 ppm/C; EIA_Code: E96; U/M: EA
R23 = CRCW06032K00FKEA: RES, 2.00 k, 1%, 0.1 W, 0603; Manufacturer: Vishay-Dale; CompType: Resistor; Value: 2.00k; Res_ohm: 2000; Value_Code: 2k00; Tolerance_%: 1; Power_W: 0.1; Value2: 0.1W; VDC_V: 75; TempCo: 100 ppm/C; EIA_Code: E96; U/M: EA
R24 = CRCW12061K00FKEA: RES, 1.00 k, 1%, 0.25 W, 1206; Manufacturer: Vishay-Dale; CompType: Resistor; Value: 1.00k; Res_ohm: 1000; Value_Code: 1k00; Tolerance_%: 1; Power_W: 0.25; Value2: 0.25W; VDC_V: 200; TempCo: 100 ppm/C; EIA_Code: E96; U/M: EA
R25 R27 = CRCW060310R0FKEA: RES, 10.0, 1%, 0.1 W, 0603; Manufacturer: Vishay-Dale; CompType: Resistor; Value: 10.0; Res_ohm: 10; Value_Code: 10R0; Tolerance_%: 1; Power_W: 0.1; Value2: 0.1W; VDC_V: 75; TempCo: 100 ppm/C; EIA_Code: E96; U/M: EA
R26 = MCR25JZHFLR160: RES, 0.16, 1%, 0.5 W, 1210; Manufacturer: Rohm; CompType: Resistor; Value: 0.16; Value_Code: R160; Tolerance_%: 1; Power_W: 0.5; Value2: 0.5W; VDC_V: 0; TempCo: 200 ppm/C; EIA_Code: E96; U/M: EA; AEC Category: Q200
R28 = CRCW12060000Z0EA: RES, 0, 5%, 0.25 W, 1206; Manufacturer: Vishay-Dale; CompType: Resistor; Value: 0; Value_Code: 0000; Tolerance_%: 5; Power_W: 0.25; Value2: 0.25W; VDC_V: 200; TempCo: 200 ppm/C; EIA_Code: E24; U/M: EA; AEC Category: Q200
TP1 TP2 = 5003: Test Point, Miniature, Orange, TH; Manufacturer: Keystone; CompType: Test Point Loop; U/M: EA
U4 = TPS92691QPWPRQ1: Multi-Topology LED Driver with Rail-to-Rail Current Sense Amplifier, PWP0016J; Alternate PartNumber: TPS92691QPWPTQ1; Manufacturer: Texas Instruments; SymbolCreator: Altium; SizeArea_mm2: 32; SizeAreaWB_mm2: 58.8; SizeX_mm: 6.4; SizeY_mm: 5; SizeZ_mm: 1.2; CompType: IC; U/M: EA

## Sheet TIDA-01183 Precision PWM LED_Hardware.SchDoc: Hardware
size 431 x 279 mm; Date: Not shown in title block; ApprovedBy: Not shown in title block; CheckedBy: Not shown in title block; Author: Not shown in title block; CompanyName: Not shown in title block; Engineer: Not shown in title block; Organization: Not shown in title block; Address1: Not shown in title block; Address2: Not shown in title block; Address3: Not shown in title block; Address4: Not shown in title block; DocumentNumber: 1; Revision: Use project parameter SCH_Rev; SheetNumber: 2; SheetTotal: 2; PageSetup: Record=PageOptions¦CenterHorizontal=True¦CenterVertical=True¦PrintScale=1.00¦XCorrection=1.00¦YCorrection=1.00¦PrintKind=0¦BorderSize=5000000¦LeftOffset=0¦BottomOffset=0¦Orientation=2¦PaperLength=1000¦PaperWidth=1000¦Scale=100¦PaperSource=15¦PrintQuality=600¦MediaType=1¦DitherType=10¦PaperKind=Letter¦PrintScaleMode=1
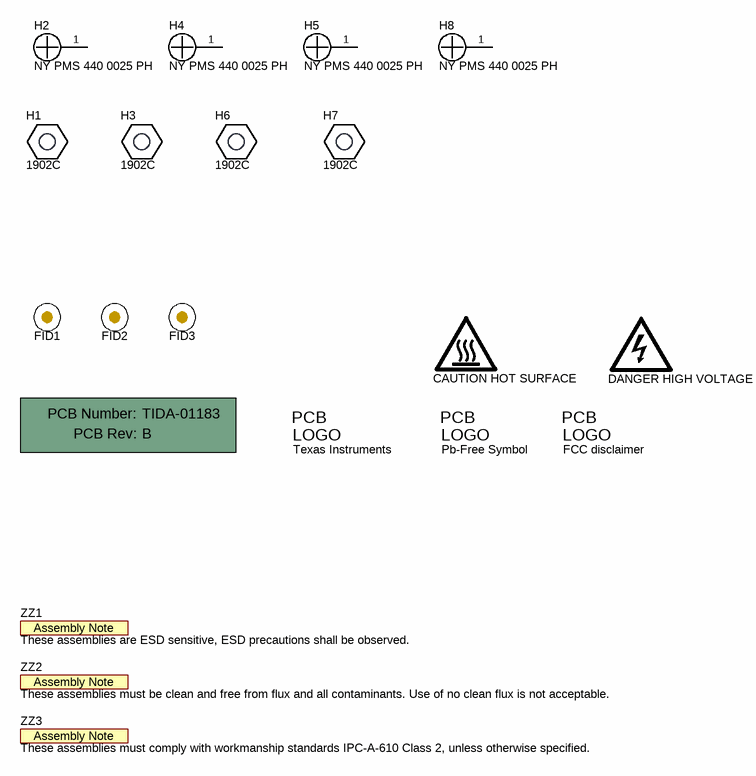
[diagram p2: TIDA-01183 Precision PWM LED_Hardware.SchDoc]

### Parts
!PCB1  Printed Circuit Board  (value not drawn)  (mechanical)
FID1  Fiducial  [Fiducial10-20]  (value not drawn)
FID2  Fiducial  [Fiducial10-20]  (value not drawn)
FID3  Fiducial  [Fiducial10-20]  (value not drawn)
H1  1902C  [Keystone_1902C]
H2  NY PMS 440 0025 PH  [NY PMS 440 0025 PH]
H3  1902C  [Keystone_1902C]
H4  NY PMS 440 0025 PH  [NY PMS 440 0025 PH]
H5  NY PMS 440 0025 PH  [NY PMS 440 0025 PH]
H6  1902C  [Keystone_1902C]
H7  1902C  [Keystone_1902C]
H8  NY PMS 440 0025 PH  [NY PMS 440 0025 PH]
Logo1  Texas Instruments  [TI_Stacked_Overlay_Small]  (no BOM)
LOGO2  CAUTION HOT SURFACE  [IEC_HotSurface_Small]  (no BOM)
Logo3  Pb-Free Symbol  [Pb-Free_Overlay_Small]  (no BOM)
Logo4  FCC disclaimer  [FCC_disclaimer]  (no BOM)
LOGO5  DANGER HIGH VOLTAGE  [IEC_HighVoltage_Small]  (no BOM)
ZZ1  These assemblies are ESD sensitive, ESD precautions shall be observed.  [AssemblyNote]  (no BOM)
ZZ2  These assemblies must be clean and free from flux and all contaminants. Use of no clean flux is not acceptable.  [AssemblyNote]  (no BOM)
ZZ3  These assemblies must comply with workmanship standards IPC-A-610 Class 2, unless otherwise specified.  [AssemblyNote]  (no BOM)

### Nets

Not connected (* = marked no-connect by the designer): H2 1; H4 1; H5 1; H8 1

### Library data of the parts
!PCB1 = PCB: Manufacturer: Any; PartNumber: TIDA-01183; SymbolCreator: a0412235
FID1-FID3 = Fiducial: Fiducial mark.  There is nothing to buy or mount.; SymbolCreator: codlsc
H1 H3 H6 H7 = 1902C: Standoff, Hex, 0.5"L #4-40 Nylon; Manufacturer: Keystone; SymbolCreator: a0412235; CompType: Hardware
H2 H4 H5 H8 = NY PMS 440 0025 PH: Machine Screw, Round, #4-40 x 1/4, Nylon, Philips panhead; Manufacturer: B&F Fastener Supply; CompType: Hardware; SymbolCreator: codlsc; U/M: EA
Logo1 = TI_Logo: Texas Instrument Corporate Signature; SymbolCreator: codlsc
LOGO2 = IEC_HotSurface: IEC 61010-1 Hot Surface Warning; SymbolCreator: a0412235
Logo3 = Pb-Free: SymbolCreator: a0412235
Logo4 = FCC_disclaimer: SymbolCreator: codlsc
LOGO5 = IEC_HighVoltage: IEC 61010-1 High Voltage Warning; SymbolCreator: a0412235
ZZ1-ZZ3 = AssemblyNote: SymbolCreator: codlsc

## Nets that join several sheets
GND: TIDA-01183 Precision PWM LED_1 (9 pins), TIDA-01183 Precision PWM LED_2 (35 pins)
VCC: TIDA-01183 Precision PWM LED_1 (R4.2), TIDA-01183 Precision PWM LED_2 (C20.1 R10.2 R12.1 U4.16)
PREC_PWM: TIDA-01183 Precision PWM LED_1 (U1.3 U2.3), TIDA-01183 Precision PWM LED_2 (R15.1 TP1.1)

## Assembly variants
001: not fitted C21 C22 FID1 FID2 FID3 R14 R28 TP3 TP4 TP5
